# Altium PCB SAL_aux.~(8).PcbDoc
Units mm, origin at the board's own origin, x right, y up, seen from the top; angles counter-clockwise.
Board outline 56 x 58 mm, 2 copper layers (Top Layer, Bottom Layer); 32 components, 48 nets, 142 pads, 9 vias.
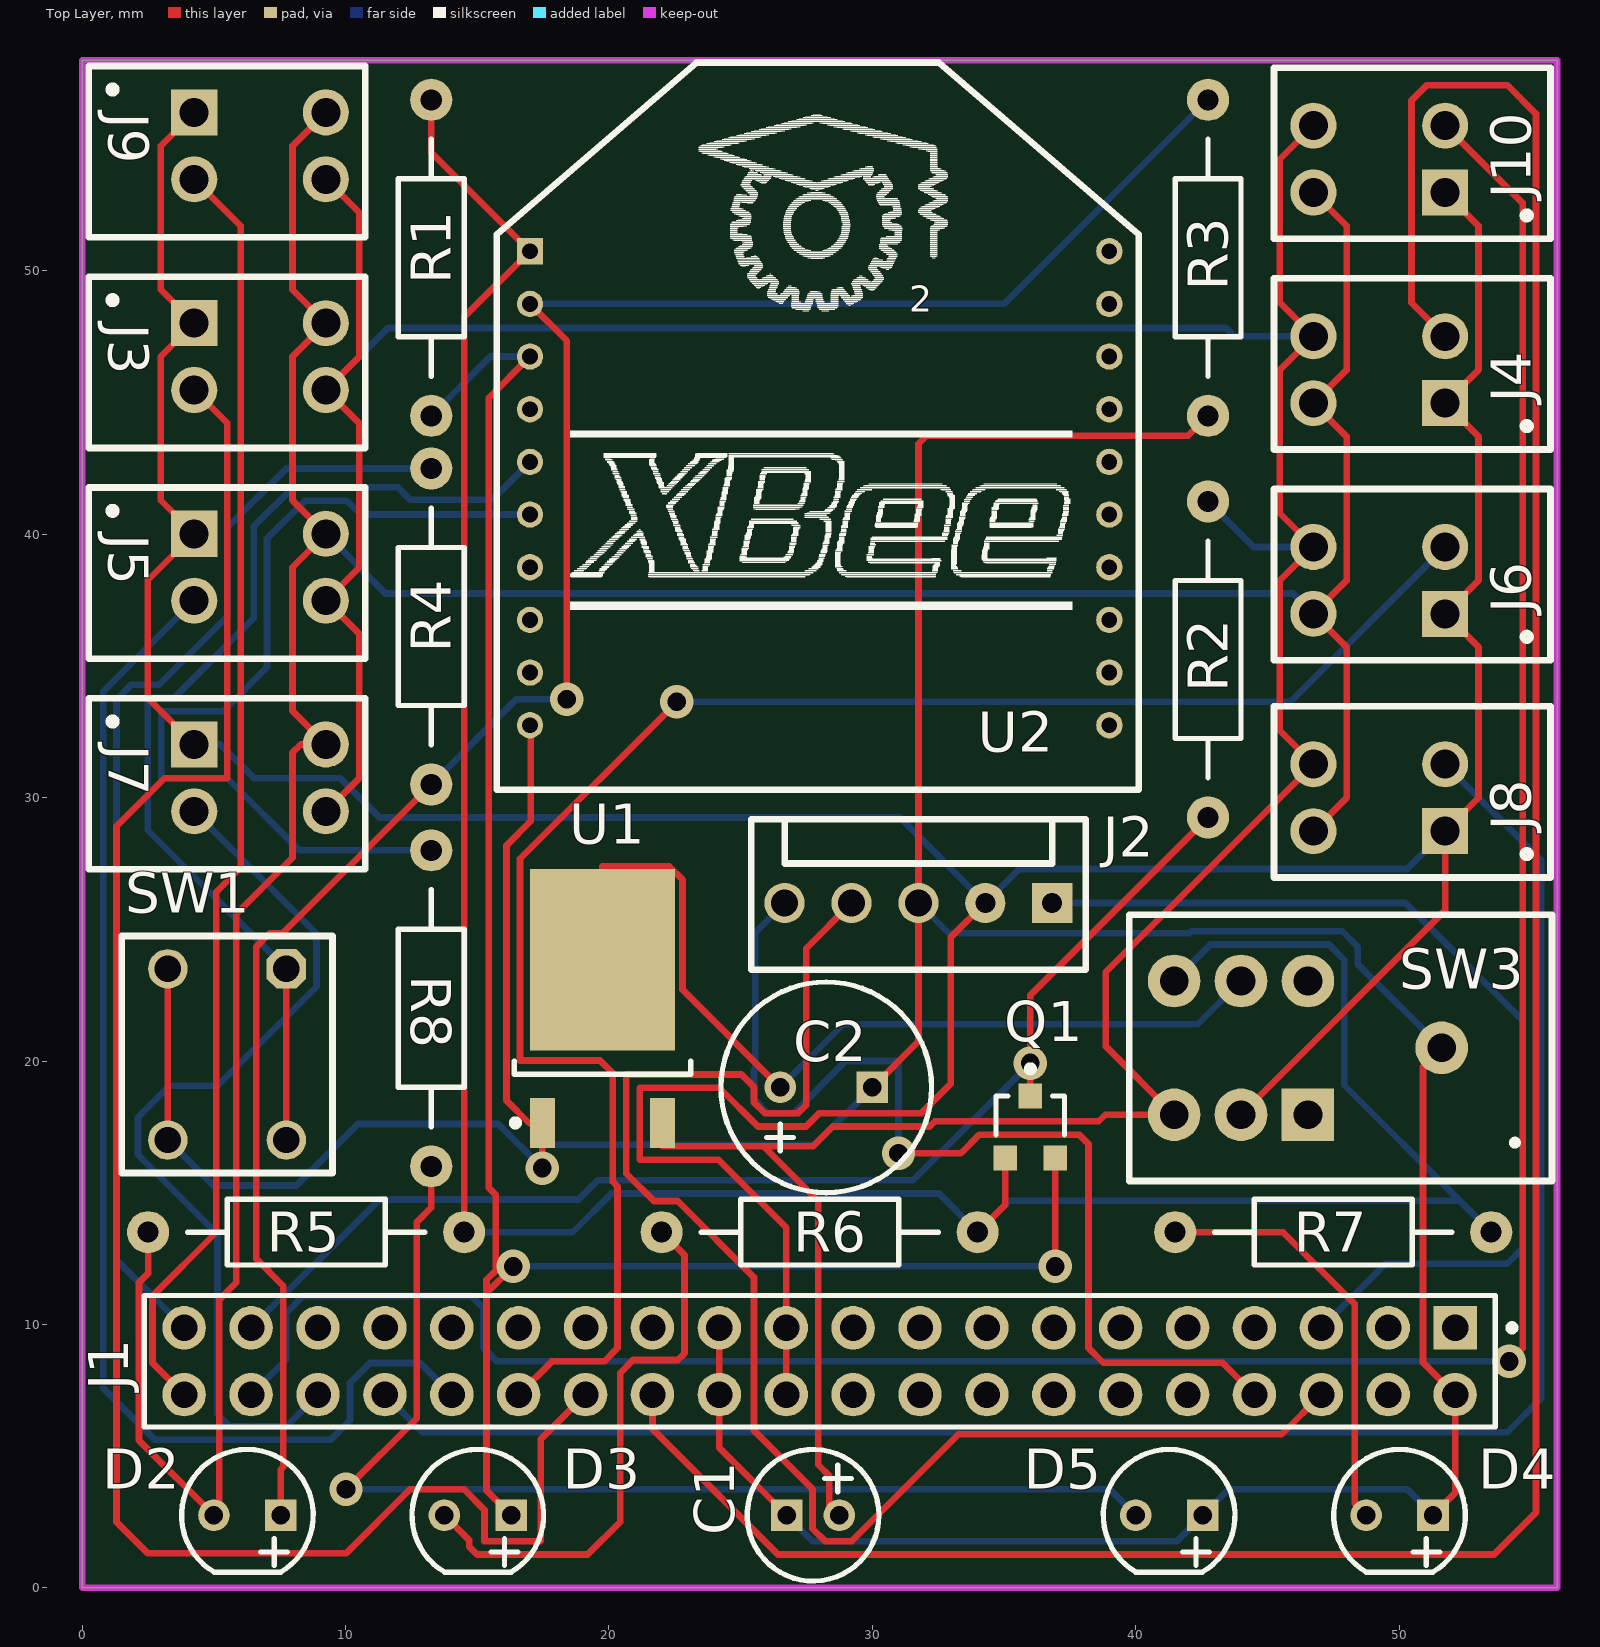
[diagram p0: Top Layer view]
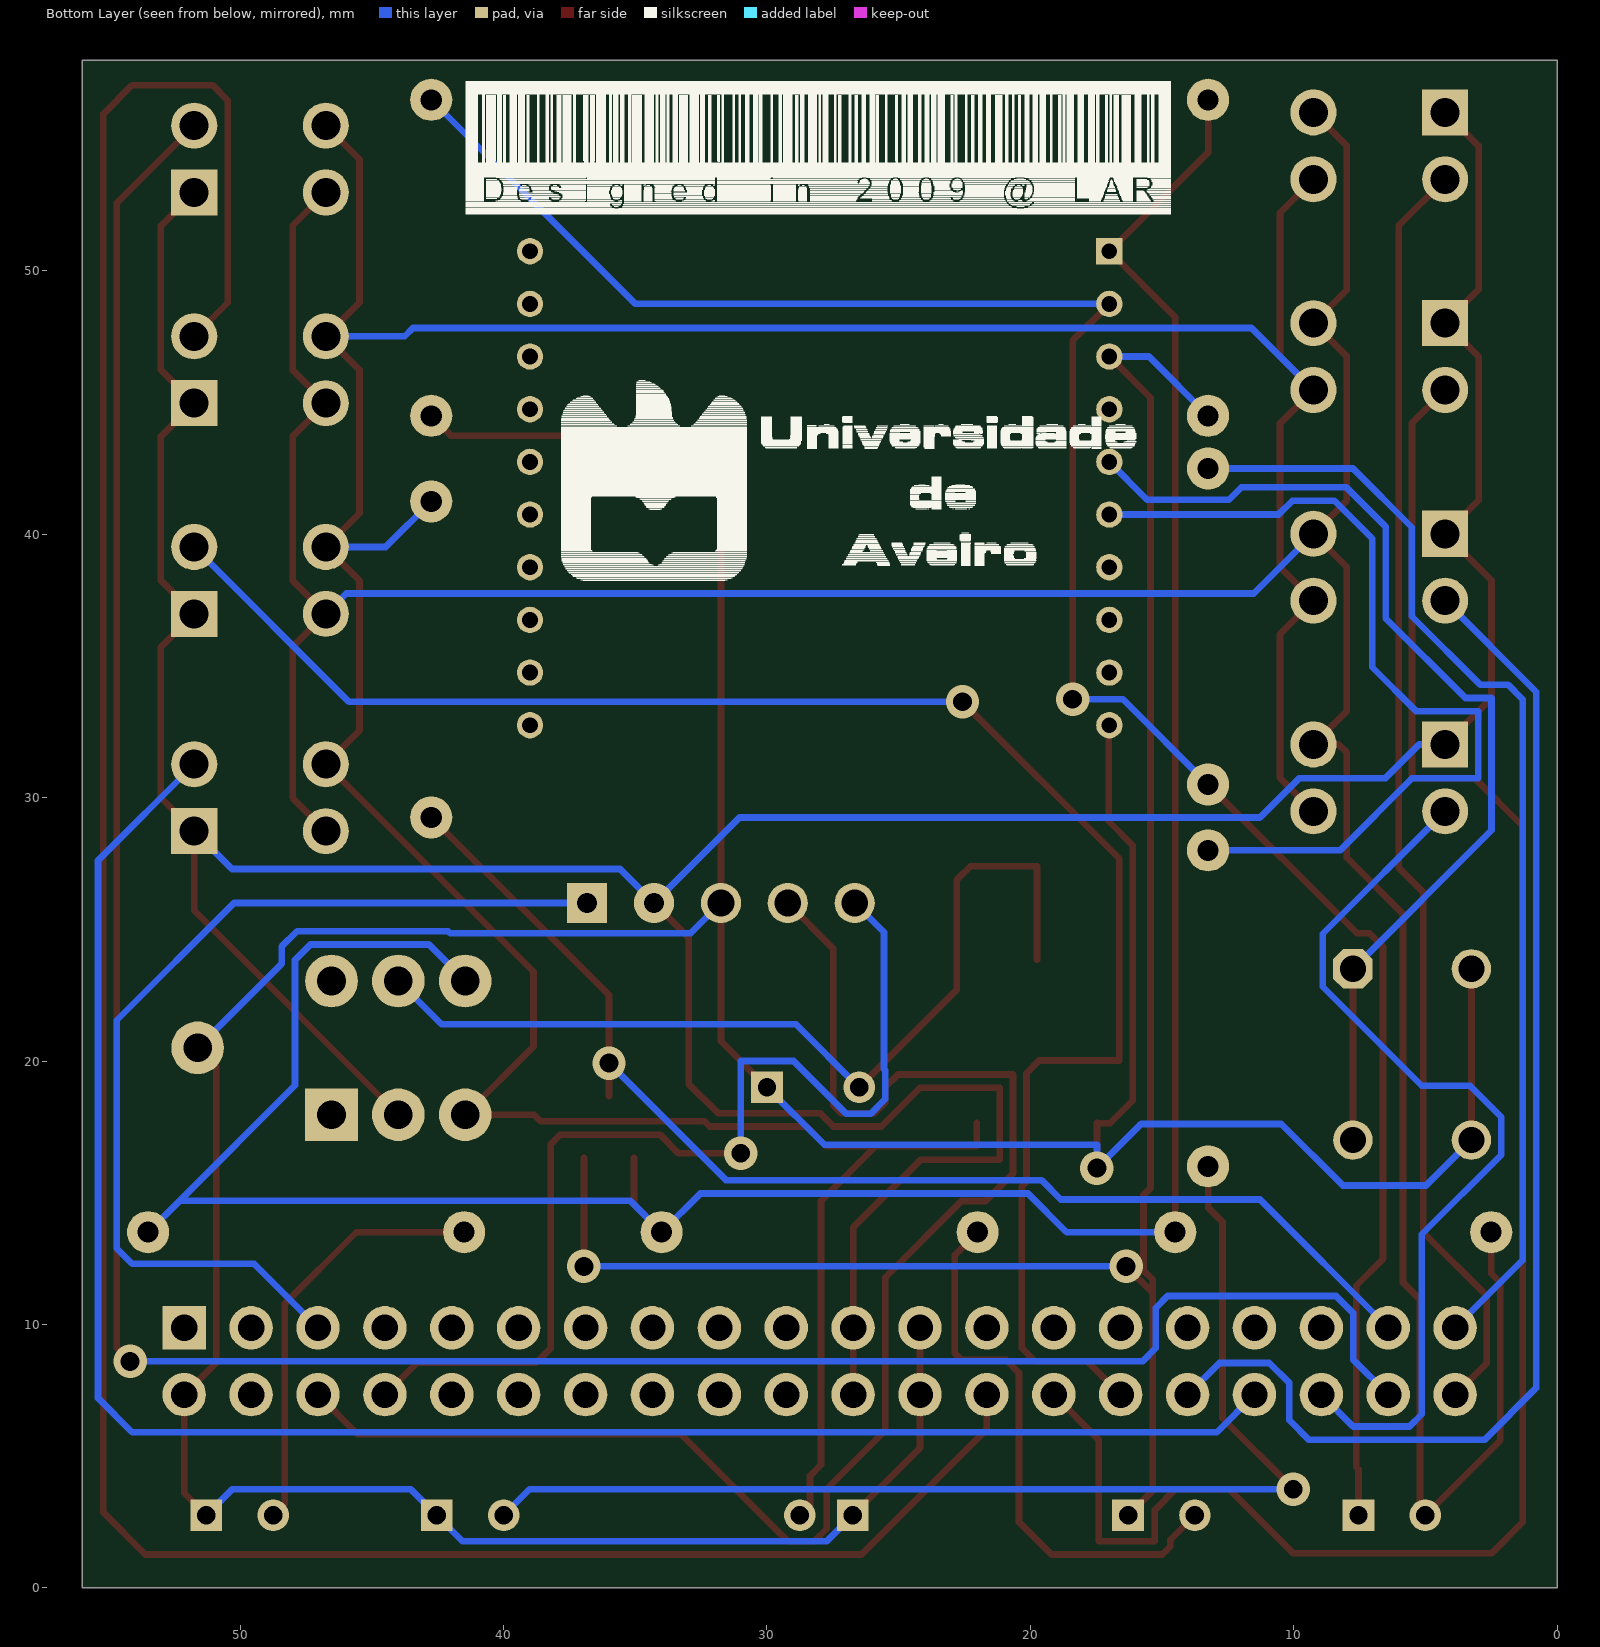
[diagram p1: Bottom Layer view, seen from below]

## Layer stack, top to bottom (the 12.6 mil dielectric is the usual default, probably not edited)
Top Layer: signal copper 0.0356
Dielectric: dielectric 0.32, FR-4, Dk 4.8
Bottom Layer: signal copper 0.0356

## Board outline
0,0 0,58 56,58 56,0

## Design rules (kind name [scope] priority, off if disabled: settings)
Clearance [All] p1: gap=0.254
PolygonConnect [All] p1: connectstyle=Relief reliefconductorwidth=0.254 reliefentries=4 polygonreliefangle="90 Angle"
RoomDefinition SAL_aux [InComponentClass('SAL_aux')] p1: confinementstyle=ConfineIn formatcopy=TRUE lockcomponents=FALSE outline 0,0 56,0 56,58 0,58
RoutingVias [All] p1: holewidth=0.711 width=1.27 viastyle="Through Hole" minholewidth=0.711 minwidth=1.27 maxholewidth=0.711 maxwidth=1.27
SilkscreenOverComponentPads [All] p1: minsilkscreentomaskgap=0.254
SolderMaskExpansion [All] p1: expansion=0.102
TestPointUsage [All] p1: valid=0 allowmultiple=FALSE
Testpoint [All] p1: side=15 testpointundercomponent=TRUE minsize=1.016 maxsize=2.54 preferedsize=1.524 minholesize=0 maxholesize=1.016 preferedholesize=0.813 testpointgrid=0.025 style=1023 order=0123456789
Width [All] p1: maxlimit=0.254 minlimit=0.254 preferedwidth=0.254
23 further rules are at their usual default settings.

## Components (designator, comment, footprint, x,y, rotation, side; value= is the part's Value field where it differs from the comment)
C1 "10 uF" "PANASONIC ECA1HAM100X" 26.75,2.75 r0 top
C2 "100 uF" "PANASONIC ECA1HAM101X" 30,19 r180 top
D2 "Yellow" "VISHAY TLLR4401" 5,2.75 r0 top
D3 "Red" "VISHAY TLLR4401" 13.75,2.75 r0 top
D4 "Green" "VISHAY TLLR4401" 48.75,2.75 r0 top
D5 "Blue" "VISHAY TLLR4401" 40,2.75 r0 top
J1 "SSW-120-01-G-D" "SAMTEC SSW-120-1-G-D" 28,8.6 r180 top
J2 "I2C Connector" "TYCO 640456-5" 31.75,26 r0 top
J3 "WAGO 234-502" "WAGO 234-502" 6.75,46.75 r270 top locked
J4 "WAGO 234-502" "WAGO 234-502" 49.25,46.25 r90 top locked
J5 "WAGO 234-502" "WAGO 234-502" 6.75,38.75 r270 top locked
J6 "WAGO 234-502" "WAGO 234-502" 49.25,38.25 r90 top locked
J7 "WAGO 234-502" "WAGO 234-502" 6.75,30.75 r270 top locked
J8 "WAGO 234-502" "WAGO 234-502" 49.25,30 r90 top locked
J9 "WAGO 234-502" "WAGO 234-502" 6.75,54.75 r270 top locked
J10 "WAGO 234-502" "WAGO 234-502" 49.25,54.25 r90 top locked
Q1 "BSS138" SOT23 36,17.5 r0 top
R1 "10K" Resistência 13.25,44.5 r90 top
R2 "10K" Resistência 42.75,29.25 r90 top
R3 "10K" Resistência 42.75,44.5 r90 top
R4 "10K" Resistência 13.25,30.5 r90 top
R5 "1K" Resistência 14.5,13.5 r180 top
R6 "1K" Resistência 34,13.5 r180 top
R7 "1K" Resistência 53.5,13.5 r180 top
R8 "1K" Resistência 13.25,28 r270 top
SW1 "OMRON B3F-1002" "OMRON B3F-1002" 5.5,20.25 r90 top
SW3 "MULTICOMP 2AD1T2A2M7RE" "MULTICOMP 2AD1T2A2M7RE" 44,20.5 r90 top
U1 "LM1117DT-3.3" TD03B_N 19.75,22 r90 top
U2 "XBee" XBee 28,40.75 r0 top locked
? "" "SAL_LOGO 2" 28,51.75 r0 top
? "" PCBComponent_1 27,42 r180 bottom
? "" Designed_logo 28,54.5 r180 bottom

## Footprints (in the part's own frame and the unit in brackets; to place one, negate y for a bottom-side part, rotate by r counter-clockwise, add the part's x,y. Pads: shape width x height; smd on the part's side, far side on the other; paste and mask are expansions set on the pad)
Designed_logo [mm]
  silkscreen extent -13.45,-2.37 13.34,2.71
"MULTICOMP 2AD1T2A2M7RE" [mm] "Switch, DPDT ON-ON"
  rect 2x2 hole 1.09: 1(-2.54,-2.54)
  round 2 hole 1.09: 2(-2.54,0) 3(-2.54,2.54) 4(2.54,-2.54) 5(2.54,0) 6(2.54,2.54) GND(0,-7.62)
  silkscreen extent -5.06,-11.81 5.06,4.25
"OMRON B3F-1002" [mm] "6.0mm Tactil Switch"
  oct 1.5x1.5 hole 1: 1(3.25,-2.25)
  round 1.5 hole 1: 2(-3.25,-2.25) 3(3.25,2.25) 4(-3.25,2.25)
  silkscreen extent -4.5,-4 4.5,4
"PANASONIC ECA1HAM100X" [mm]
  rect 1.2x1.2 hole 0.7: 1(0,0)
  round 1.2 hole 0.7: 2(2,0)
  silkscreen extent -1.5,-2.5 3.5,2.5
"PANASONIC ECA1HAM101X" [mm]
  rect 1.2x1.2 hole 0.7: 1(0,0)
  round 1.2 hole 0.7: 2(3.5,0)
  silkscreen extent -2.25,-4 5.75,4
PCBComponent_1 [mm]
  silkscreen extent -10.82,-3.77 11.02,3.85
Resistência [mm]
  round 1.6 hole 0.8: 1(0,0) 2(12,0)
  silkscreen extent 1.5,-1.25 10.5,1.25
"SAL_LOGO 2" [mm]
  silkscreen extent -4.6,-3.28 4.88,4.19
"SAMTEC SSW-120-1-G-D" [mm]
  rect 1.65x1.65 / inner round 1.65 / far side rect 1.65x1.65 hole 1 mask+0: 1(-24.13,-1.27)
  round 1.65 hole 1 mask+0: 2(-24.13,1.27) 3(-21.59,-1.27) 4(-21.59,1.27) 5(-19.05,-1.27) 6(-19.05,1.27) 7(-16.51,-1.27) 8(-16.51,1.27) 9(-13.97,-1.27) 10(-13.97,1.27) 11(-11.43,-1.27) 12(-11.43,1.27) 13(-8.89,-1.27) 14(-8.89,1.27) 15(-6.35,-1.27) 16(-6.35,1.27) 17(-3.81,-1.27) 18(-3.81,1.27) 19(-1.27,-1.27) 20(-1.27,1.27) 21(1.27,-1.27) 22(1.27,1.27) 23(3.81,-1.27) 24(3.81,1.27) 25(6.35,-1.27) 26(6.35,1.27) 27(8.89,-1.27) 28(8.89,1.27) 29(11.43,-1.27) 30(11.43,1.27) 31(13.97,-1.27) 32(13.97,1.27) 33(16.51,-1.27) 34(16.51,1.27) 35(19.05,-1.27) 36(19.05,1.27) 37(21.59,-1.27) 38(21.59,1.27) 39(24.13,-1.27) 40(24.13,1.27)
  silkscreen extent -26.41,-2.5 25.65,2.5
SOT23 [mm] "SOT-23; 3 Leads; Body 3.1 x 2.5 mm, inc. leads (LxW max), Alternate Lead Configuration"
  rect 0.9x0.95 smd: 1(0,1.175) 2(0.95,-1.175) 3(-0.95,-1.175)
  silkscreen extent -1.3,-0.3 1.3,2.32
TD03B_N [mm] "D-PAK, 4-Leads, Body 6.1x6.6mm, Pitch 2.29mm, Lead Span 9.7mm, IPC Medium Density"
  rect 1.9x0.95 smd: 1(-4.35,2.28) 3(-4.35,-2.28)
  rect 6.9x5.5 smd: 4(1.85,0)
  silkscreen extent -4.47,-3.35 -2,3.43
"TYCO 640456-5" [mil] "I2C Connector"
  rect 60x60 hole 30: 1(200,0)
  round 60 hole 30: 2(100,0)
  round 60 hole 40.16: 3(0,0) 4(-100,0) 5(-200,0)
  silkscreen extent -250,-100 250,125
"VISHAY TLLR4401" [mm] "3mm LED"
  round 1.2 hole 0.7: 1(0,0)
  rect 1.2x1.2 hole 0.7: 2(2.54,0)
  silkscreen extent -1.23,-2.17 3.77,2.5
"WAGO 234-502" [mm]
  rect 1.75x1.75 hole 1.1: 1(-1.27,-2.5)
  round 1.75 hole 1.1: 2(-1.27,2.5) 3(1.27,-2.5) 4(1.27,2.5)
  silkscreen extent -3.03,-6.5 3.47,4
XBee [mm] "ZigBee device"
  rect 1x1 hole 0.6: 1(-11,10)
  round 1 hole 0.6: 2(-11,8) 3(-11,6) 4(-11,4) 5(-11,2) 6(-11,0) 7(-11,-2) 8(-11,-4) 9(-11,-6) 10(-11,-8) 11(11,-8) 12(11,-6) 13(11,-4) 14(11,-2) 15(11,0) 16(11,2) 17(11,4) 18(11,6) 19(11,8) 20(11,10)
  silkscreen extent -12.26,-10.44 12.12,17.17

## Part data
C1: library part "PANASONIC ECA1HAM100X"
C2: library part "PANASONIC ECA1HAM101X"
D2 D3 D4 D5: library part "VISHAY TLLG4401", "Green LED PCB 3mm"
J1: library part "SAMTEC SSW-120-01-G-D"
J2: library part "TYCO 640456-5"
Q1: "N-Channel Enhancement Mode Vertical DMOS FET"
R1 R2 R3 R4 R5 R6 R7 R8: library part Resistência
SW1: "6.0mm Tact Switch"
U1: "800mA Low-Dropout Linear Regulator"

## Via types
v1: diameter 1.27, hole 0.711, Top Layer to Bottom Layer, 9 vias

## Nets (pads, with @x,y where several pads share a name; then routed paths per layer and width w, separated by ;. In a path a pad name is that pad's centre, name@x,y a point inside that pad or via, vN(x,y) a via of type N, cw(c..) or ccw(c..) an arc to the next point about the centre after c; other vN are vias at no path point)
1: D2.1 J3.2 J4.2 J5.2 J6.2 J7.2 J8.2 J9.2 J10.2 R5.2 | length 137
  Top Layer w0.254: R5.2 2.5,11.928 2.156,11.584 2.156,5.594 D2.1 5.204,2.954 5.204,10.947 5.848,11.591 5.848,25.587 7.982,27.72 7.982,31.708 8.294,32.02 J7.2 7.982,33.288 7.982,38.752 J5.2 7.982,41.288 7.982,46.752 J3.2 7.982,49.288 7.982,54.752 J9.2 ; J8.2 48.012,29.992 48.012,35.718 J6.2 48.012,38.242 48.012,43.718 J4.2 48.012,46.242 48.012,51.718 J10.2
  Bottom Layer w0.254: J5.2 11.517,37.753 45.977,37.753 J6.2
3.3V: Q1.3 R1.2 R5.1 R6.1 R7.1 SW3.6 U2.1 | length 110
  Top Layer w0.254: R1.2 13.25,54.5 U2.1 14.5,48.25 R5.1 ; R6.1 35.05,14.55 Q1.3
  Bottom Layer w0.254: R5.1 18.622,13.5 20.091,14.969 32.531,14.969 R6.1 35.19,14.69 52.31,14.69 ; SW3.6 42.841,24.421 47.334,24.421 47.921,23.834 47.921,19.079 52.31,14.69 ; 52.31,14.69 R7.1 52.31,14.69
"3.3V OUT": C2.2 SW3.5 U1.4 | length 35.4
  Top Layer w0.254: U1.4 19.75,27.39 22.282,27.39 22.786,26.886 22.79,26.882 22.79,22.71 C2.2
  Bottom Layer w0.254: C2.2 28.896,21.396 42.356,21.396 SW3.5
/INT: J1.20
/RESET: J1.5 J2.1 | length 37.3
  Bottom Layer w0.254: J2.1 50.24,26 54.692,21.548 54.692,12.887 54.108,12.302 49.482,12.302 J1.5
A0: J1.7
A4/LSDA: J1.1
A5/LSCL: J1.3
B5: J1.10
C0: J1.25
C1: J1.27
C2: J1.29
C5: J1.35
D0: J1.40 J9.3 | length 48.8
  Top Layer w0.254: J1.40 2.664,8.536 2.664,11.076 5.086,13.498 5.086,26.425 6.014,27.353 6.014,51.716 J9.3
D1: J1.38 J10.3 | length 100.6
  Top Layer w0.254: J10.3 54.692,52.578 54.692,9.102 v1(54.184,8.594)
  Bottom Layer w0.254: J1.38 7.744,8.664 7.744,10.432 8.388,11.076 14.786,11.076 15.236,10.626 15.236,9.102 15.744,8.594 v1(54.184,8.594)
D2: J1.36 J7.3 | length 34.5
  Bottom Layer w0.254: J7.3 8.896,24.834 8.896,22.818 5.137,19.059 3.308,19.059 2.114,17.865 2.114,16.443 5.137,13.42 5.137,6.587 5.6,6.124 7.744,6.124 J1.36
D3: J1.34 J8.3 | length 70.6
  Bottom Layer w0.254: J1.34 12.918,5.902 54.108,5.902 55.403,7.197 55.403,27.617 J8.3
D4: J1.32 J5.3 | length 47.9
  Bottom Layer w0.254: J5.3 0.793,34.023 0.793,7.578 2.755,5.616 9.423,5.616 10.166,6.359 10.166,7.774 10.928,8.536 12.824,8.536 J1.32
D5: J1.30 J6.3 | length 66.4
  Top Layer w0.254: J1.30 17.834,8.594 19.818,8.594 20.326,9.102 20.326,15.238 20.148,15.416 20.148,19.536 19.666,20.019 16.619,20.019 16.619,27.681 v1(22.576,33.638)
  Bottom Layer w0.254: v1(22.576,33.638) 45.868,33.638 J6.3
D6: J1.28 J3.3 | length 72
  Top Layer w0.254: J3.3 5.506,44.224 5.506,30.743 3.13,30.743 1.301,28.914 1.301,2.498 2.495,1.304 10.014,1.304 12.452,3.743 14.484,3.743 15.271,2.955 15.271,1.769 17.405,1.769 17.405,5.625 J1.28
D7: J1.26 J4.3 | length 105.5
  Top Layer w0.254: J1.26 21.65,6.025 26.414,1.261 53.608,1.261 55.2,2.854 55.2,55.965 54.108,57.057 51.06,57.057 50.476,56.473 50.476,48.794 J4.3
DIN: D3.2 Q1.2 R1.1 U2.3 | length 83.6
  Top Layer w0.254: D3.2 15.348,3.692 ; v1(16.364,12.201) 15.348,11.185 ; U2.3 15.438,45.188 15.438,15.184 15.703,14.919 15.703,12.201 15.703,12.048 15.348,11.693 15.348,11.185 ; v1(36.95,12.201) Q1.2 ; 15.348,3.692 15.348,11.185 ; 15.348,3.692 15.348,11.185
  Bottom Layer w0.254: R1.1 15.5,46.75 U2.3 ; v1(16.364,12.201) v1(36.95,12.201)
DOUT: D2.2 R3.2 R4.1 U2.2 | length 82.3
  Top Layer w0.254: D2.2 7.54,4.495 7.626,4.581 7.626,11.464 6.61,12.48 6.61,24.342 7.118,24.85 7.6,24.85 R4.1 ; U2.2 18.396,47.354 v1(18.396,33.74)
  Bottom Layer w0.254: R4.1 16.49,33.74 v1(18.396,33.74) ; U2.2 35,48.75 R3.2
EYEB: J1.19
EYEF: J1.9
EYEL: J1.13
EYER: J1.11
NetD3_1: D3.1 R6.2 | length 21.3
  Top Layer w0.254: D3.1 14.688,1.812 14.688,1.565 14.992,1.261 19.191,1.261 20.428,2.498 20.428,8.159 20.913,8.645 22.612,8.645 22.866,8.899 22.866,12.634 R6.2
NetD4_1: D4.1 R7.2 | length 16.2
  Top Layer w0.254: R7.2 45.595,13.5 48.317,10.778 48.317,3.183 D4.1
NetD5_1: D5.1 R8.2 | length 44
  Top Layer w0.254: v1(10.014,3.743) 12.706,6.435 12.706,13.892 13.25,14.436 R8.2
  Bottom Layer w0.254: v1(10.014,3.743) 39.007,3.743 D5.1
PWM1/SERVOR: J1.18
PWM2/SERVOL: J1.16
PWM3: J1.14
PWM4: J1.12
RESET: SW1.1 SW1.2 U2.5 | length 39.6
  Top Layer w0.254: SW1.2 SW1.1
  Bottom Layer w0.254: SW1.1 2.486,28.764 2.486,33.784 3.479,33.784 6.508,36.813 6.508,40.293 7.999,41.784 11.993,41.784 12.468,41.309 15.559,41.309 U2.5
RSSI: R8.1 U2.6 | length 34.3
  Bottom Layer w0.254: R8.1 8.242,28 5.506,30.736 2.994,30.736 2.994,33.276 5.34,33.276 7.016,34.952 7.016,39.836 8.456,41.276 10.047,41.276 10.573,40.75 U2.6
RX: J1.39 R4.2 | length 42.5
  Bottom Layer w0.254: J1.39 1.301,12.439 1.301,33.727 1.867,34.292 2.92,34.292 5.518,36.89 5.518,40.268 7.75,42.5 R4.2
SCL: J1.31
SDA: J1.33
TX: J1.37 Q1.1 R2.1 | length 48.4
  Top Layer w0.254: R2.1 36,22.5 v1(36,19.922) ; v1(36,19.922) Q1.1 v1(36,19.922)
  Bottom Layer w0.254: J1.37 11.281,14.741 18.847,14.741 19.583,15.477 31.555,15.477 v1(36,19.922)
US_B: J1.17
US_F: J1.15
V+: J1.4
VDD: J1.21 J1.22 J2.2 J3.1 J4.1 J5.1 J6.1 J7.1 J8.1 J9.1 J10.1 SW3.2 | length 156.3
  Top Layer w0.254: J7.1 2.486,33.784 2.486,38.256 J5.1 2.978,41.292 2.978,46.748 J3.1 2.978,49.292 2.978,54.748 J9.1 ; J1.22 J1.21 26.73,13.674 24.15,16.254 21.164,16.254 21.164,18.983 24.188,18.983 25.66,17.511 27.481,17.511 27.989,18.019 31.867,18.019 32.975,19.127 32.975,24.685 J2.2 ; SW3.2 51.75,25.71 J8.1 53.016,29.996 53.016,35.714 J6.1 53.016,38.246 53.016,43.714 J4.1 53.016,46.246 53.016,51.714 J10.1
  Bottom Layer w0.254: J7.1 5.238,32.02 6.515,30.743 9.785,30.743 11.284,29.244 31.046,29.244 J2.2 35.578,27.288 50.308,27.288 J8.1
"VDD OUT": C1.2 J3.4 J4.4 J5.4 J6.4 J7.4 J8.4 J9.4 J10.4 R2.2 SW3.3 U1.3 | length 155.4
  Top Layer w0.254: J7.4 10.522,30.752 10.522,36.208 J5.4 10.522,38.752 10.522,44.208 J3.4 10.522,46.752 10.522,52.208 J9.4 ; U1.3 U1.3@22.03,16.762 ; C1.2 28.37,3.13 28.37,4.246 27.946,4.67 27.946,14.69 25.874,16.762 ; J10.4 45.472,54.242 45.472,48.798 J4.4 45.472,46.242 45.472,40.798 J6.4 45.472,38.242 45.472,32.548 J8.4 38.868,23.388 38.868,20.552 SW3.3 38.843,17.96 38.595,17.713 32.375,17.713 32.174,17.511 28.497,17.511 27.748,16.762 25.874,16.762 ; U1.3@22.03,16.762 25.874,16.762 ; U1.3@22.03,16.762 25.874,16.762
  Bottom Layer w0.254: J3.4 11.607,47.837 43.44,47.837 43.757,47.52 J4.4 ; R2.2 44.48,39.52 J6.4
VSS: C1.1 C2.1 D4.2 D5.2 J1.2 J1.23 J1.24 J2.3 R3.1 SW1.3 SW1.4 SW3.GND U1.1 U2.10 | length 168
  Top Layer w0.254: SW1.4 SW1.3 ; U2.10 17.024,32.75 17.024,29.102 16.111,28.189 16.111,18.499 16.973,17.636 U1.1@17.47,17.636 ; v1(17.47,15.935) U1.1@17.47,17.636 ; J1.23 J1.24 24.19,5.31 C1.1 ; C2.1 31.75,20.75 J2.3 31.75,43.437 32.061,43.748 41.998,43.748 R3.1 ; D4.2 52.13,3.59 J1.2 50.908,8.552 50.908,19.788 SW3.GND ; U1.1@17.47,17.636 U1.1 U1.1@17.47,17.636
  Bottom Layer w0.254: SW1.4 4.976,15.274 8.134,15.274 10.471,17.611 15.794,17.611 v1(17.47,15.935) 17.47,16.824 27.824,16.824 C2.1 ; C1.1 27.739,1.761 41.551,1.761 D5.2 43.533,3.743 50.297,3.743 D4.2 ; J2.3 32.9,24.85 42.032,24.85 42.111,24.929 47.842,24.929 48.429,24.342 48.429,23.691 SW3.GND
XAXIS: J1.8 J2.5 | length 40.4
  Top Layer w0.254: v1(30.994,16.493) 33.356,16.493 34.067,17.205 37.852,17.205 38.208,16.849 38.208,9.102 38.766,8.543 43.297,8.543 J1.8
  Bottom Layer w0.254: J2.5 25.558,24.888 25.558,19.694 25.508,19.643 25.508,18.551 26.066,17.992 26.981,17.992 28.987,19.999 30.994,19.999 v1(30.994,16.493)
YAXIS: J1.6 J2.4 | length 58.8
  Top Layer w0.254: J2.4 27.489,24.279 27.489,18.324 27.184,18.019 25.914,18.019 25.508,18.425 25.508,19.008 25.025,19.491 20.656,19.491 20.656,15.731 21.707,14.681 22.612,14.681 25.508,11.785 25.508,5.966 27.731,3.743 27.731,2.238 28.2,1.769 29.216,1.769 33.272,5.825 45.545,5.825 J1.6
pads on no net: SW3.1 SW3.4 U2.4 U2.7 U2.8 U2.9 U2.11 U2.12 U2.13 U2.14 U2.15 U2.16 U2.17 U2.18 U2.19 U2.20

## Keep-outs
Top Layer:
  the board outline again, w0.254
